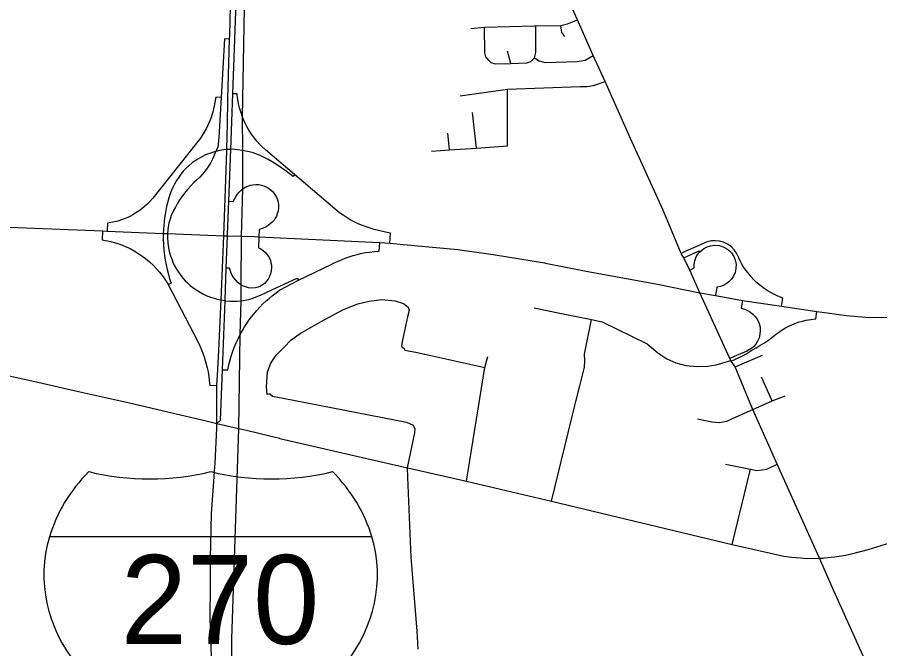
# Model space of a CAD drawing. Extents: x 1755200 to 1902939, y 644115 to 788070.
# Drawn here: x 1792682 to 1802380, y 715838 to 722940 of the extents above; entities that cross this region are included whole.
import ezdxf

# ---------------------------------------------------------------- set-up
doc = ezdxf.new("R2010")
doc.units = 0
for name, color, linetype in [('GM_X_City_Street', 7, 'Continuous'), ('GM_X_County_Road', 7, 'Continuous'), ('GM_X_Interchange_Ramps', 7, 'Continuous'), ('GM_X_Interstate_Route', 7, 'Continuous'), ('GM_X_Interstate_Shield', 7, 'Continuous'), ('GM_X_Township', 7, 'Continuous')]:
    doc.layers.add(name, color=color, linetype=linetype)

msp = doc.modelspace()

# ---------------------------------------------------------------- linework, layer by layer
at = {"layer": 'GM_X_City_Street'}
for points in [[(1799922.1, 720819), (1799578.3, 721577.4), (1799292.9, 722218.4), (1799156.2, 722510.8), (1798981.2, 722912.2), (1798799.7, 723311.4), (1798618.3, 723721.3), (1798281.2, 724477)], [(1797783.5, 722813.8), (1797937.3, 722828.9), (1798497.6, 722843.5)], [(1797984.3, 722455.3), (1797950.1, 722495.9), (1797938.4, 722540.5), (1797937.3, 722828.9)], [(1798497.6, 722843.5), (1798511.6, 722843.9), (1798793.4, 722848.1), (1798870.2, 722865.2), (1798981.2, 722912.2)], [(1798498.7, 722485.2), (1798513.7, 722545), (1798511.6, 722843.9)], [(1798838.2, 722724.3), (1798806.1, 722769.2), (1798793.4, 722848.1)], [(1798231.9, 722419.1), (1798192.9, 722556.6)], [(1797984.3, 722455.3), (1798007.7, 722429.7), (1798056.8, 722414.8), (1798231.9, 722419.1), (1798413.3, 722425.5), (1798456, 722440.4), (1798498.7, 722485.2)], [(1798498.7, 722485.2), (1798550, 722448.9), (1798616.2, 722431.9), (1798740, 722434), (1798979.1, 722440.4), (1799068.7, 722457.5), (1799156.2, 722510.8)], [(1797662.7, 722056.2), (1798193.5, 722130.8), (1799013.2, 722160.7), (1799087.9, 722160.7), (1799160.5, 722173.6), (1799292.9, 722218.4)], [(1798195.6, 721494.8), (1798193.5, 722130.8)], [(1797845.9, 721469.3), (1797801.9, 721867)], [(1797543.6, 721447.2), (1797523.9, 721636.6)], [(1797340.2, 721432.3), (1797543.6, 721447.2), (1797845.9, 721469.3), (1798195.6, 721494.8)], [(1800045.9, 720527.8), (1799941.2, 720777), (1799922.1, 720819)], [(1800948.6, 718535.3), (1800753.9, 719007.9), (1800708.9, 719072), (1800705, 719079.7), (1800693, 719103.5), (1800357.9, 719840.5), (1800244.5, 720096.6), (1800177.4, 720232.6), (1800148.1, 720284.6), (1800045.9, 720527.8)], [(1795521.6, 718706.5), (1795493, 718698.3), (1795483.1, 718784.8), (1795495.2, 718953), (1795533.7, 719050.4), (1795592, 719141.2), (1795684.5, 719231.2), (1795762.6, 719311.5), (1795862.7, 719383.3), (1796090.5, 719514.1), (1796350.5, 719652.1), (1796510.5, 719716.3), (1796637.6, 719747.3), (1796776.5, 719766), (1796930.5, 719750.1), (1797024, 719719.8), (1797077.2, 719680.3), (1797088.3, 719641.9), (1797070.5, 719572.2), (1797012, 719308.8), (1797007, 719268.8), (1797004.2, 719236.8), (1797033.7, 719214)], [(1798492.7, 719672.1), (1798764.4, 719615), (1799138.2, 719540), (1799257.6, 719514), (1799763.2, 719266.6), (1799884.2, 719166), (1799984.7, 719096.8), (1800088.6, 719053.5), (1800198.2, 719024.9), (1800325.1, 719013), (1800443.9, 719017.4), (1800540.3, 719032.5), (1800705, 719079.7)], [(1798963.2, 718617.1), (1799007, 718794.4), (1799059.2, 719004.4), (1799063.4, 719079.1), (1799060.9, 719152.2), (1799138.2, 719540)], [(1790084.9, 719483.7), (1790089.4, 719482.8), (1790568.8, 719379), (1790869, 719309), (1791383, 719177.3), (1791626.9, 719116.3), (1792323, 718971.1), (1792577.4, 718912.4), (1792962.2, 718825.1)], [(1797033.7, 719214), (1797037.3, 719195.8), (1797163.1, 719174.7), (1797262.7, 719152.4)], [(1797262.7, 719152.4), (1797264.5, 719152), (1797941, 719001.1)], [(1800753.9, 719007.9), (1801059.6, 719139.3)], [(1797731.7, 717722.3), (1797941, 719001.1), (1797972.1, 719124.6)], [(1801168.2, 718626.3), (1801050.6, 718892.1)], [(1792962.2, 718825.1), (1793370, 718732.6), (1793943.5, 718601.8), (1794758.7, 718410.9), (1794760.1, 718410.6)], [(1795521.6, 718706.5), (1795553.7, 718680.3), (1795673, 718657), (1797059.1, 718386.2), (1797131.9, 718351.3)], [(1800951, 718529.6), (1801168.2, 718626.3), (1801316, 718680.4)], [(1798688.8, 717498.6), (1798952, 718572), (1798963.2, 718617.1)], [(1800329.8, 718424), (1800490.2, 718391.4), (1800575.4, 718381.5), (1800659.4, 718398.6), (1800763.6, 718444.2), (1800951, 718529.6)], [(1801783.4, 712231.7), (1801887.9, 712659.7), (1801997.9, 713163.1), (1802166.2, 713923.2), (1802256.5, 714341), (1802306.7, 714573.8), (1802366, 714854.1), (1802375.2, 714962.6), (1802376.2, 715028.5), (1802376.2, 715109.6), (1802372.8, 715188.8), (1802350.8, 715313.4), (1802311.5, 715466.5), (1802266.9, 715592.7), (1802098.4, 715964.8), (1801848.6, 716523.8), (1801702.5, 716856.8), (1801227.1, 717912.4), (1800951, 718529.6), (1800948.6, 718535.3)], [(1795170.9, 718315.3), (1795173.2, 718314.8), (1795273.4, 718290.7)], [(1795273.4, 718290.7), (1795632.2, 718204.6)], [(1797070.7, 717873.7), (1797152.2, 718266.8), (1797158.1, 718310.5), (1797131.9, 718351.3)], [(1795632.2, 718204.6), (1795633.7, 718204.2), (1797070.7, 717873.7)], [(1800643.6, 717914.1), (1800927.2, 717856.8), (1800996.4, 717843.2), (1801108.2, 717859.2), (1801227.1, 717912.4)], [(1797070.7, 717873.7), (1797122.1, 717861.9)], [(1797075.1, 717769), (1797070.7, 717873.7)], [(1797122.1, 717861.9), (1797731.7, 717722.3), (1798688.8, 717498.6), (1800720.5, 717010.2), (1801299.7, 716878.2), (1801392.7, 716866.2), (1801488.8, 716860.2), (1801560.8, 716854.2), (1801702.5, 716856.8)], [(1800720.5, 717010.2), (1800927.2, 717856.8)], [(1801702.5, 716856.8), (1801742.3, 716857.2), (1801756.4, 716858.8)]]:
    msp.add_lwpolyline(points, dxfattribs=at)
at = {"layer": 'GM_X_County_Road'}
for points in [[(1794760.1, 718410.6), (1794927.6, 718370.2), (1795170.9, 718315.3)], [(1797189, 715833.2), (1797177, 716035.5), (1797112.4, 716867.6), (1797075.1, 717769)], [(1801756.4, 716858.8), (1801874.4, 716872.2), (1801992.9, 716891.7), (1802093.5, 716911.2), (1802251, 716954.7), (1802491.1, 717027.5)]]:
    msp.add_lwpolyline(points, dxfattribs=at)
at = {"layer": 'GM_X_Interchange_Ramps'}
for points in [[(1794927.6, 718370.2), (1794966.4, 718408), (1794988.4, 718973.1), (1795018.8, 719753), (1795033.1, 720119.2), (1795047.2, 720481), (1795047.8, 720496.4), (1795061.4, 720870.5), (1795082.5, 721454.1), (1795105.1, 722080.1), (1795142.2, 723105.2), (1795083.1, 723108)], [(1795069.1, 722693.1), (1795011.5, 722695.9), (1794975.3, 722036.8), (1794950.6, 721588.5), (1794939.4, 721478), (1794916.6, 721431.1), (1794905.7, 721408.8), (1794880.8, 721353.1), (1794858, 721308), (1794838.9, 721275.2), (1794809.6, 721231.2), (1794784.2, 721197.8), (1794762.1, 721171.6), (1794734.1, 721141.6), (1794698, 721109.2), (1794667.7, 721080.2), (1794634, 721045.2), (1794597.6, 721004.2), (1794563.3, 720961.8), (1794533, 720920.7), (1794508.5, 720884.7), (1794482.2, 720842.7), (1794460.2, 720804.3), (1794436.5, 720759), (1794413.3, 720709.2), (1794399.9, 720670.7), (1794388.4, 720624.7), (1794380.5, 720581.4), (1794376.3, 720547.5), (1794373.4, 720507.5), (1794373, 720501.5), (1794372.6, 720463.1), (1794376.3, 720400.1), (1794383.6, 720347.8), (1794392.1, 720306.6), (1794406.2, 720255.7), (1794419, 720218.9), (1794432.1, 720186.6), (1794451.4, 720145.7), (1794472.7, 720107), (1794493.8, 720073.4), (1794520.5, 720036.1), (1794546.9, 720003.4), (1794570.9, 719976.9), (1794596.3, 719951.5), (1794627, 719923.9), (1794666.8, 719892.4), (1794700.2, 719869.3), (1794737.8, 719846.4), (1794776.2, 719826.2), (1794815.7, 719808.2), (1794865.4, 719789.6), (1794899.2, 719779.2), (1794930.5, 719771), (1794970.9, 719761.3), (1794974.9, 719760.6), (1795018.8, 719753), (1795022.4, 719752.4), (1795070.7, 719747.6), (1795108.6, 719746.3), (1795154.1, 719747.3), (1795201.2, 719751.5), (1795245.6, 719758.5), (1795283.1, 719766.7), (1795323.1, 719777.9), (1795370.3, 719794.4), (1795415.7, 719814.1), (1795543.6, 719874.2), (1795830.2, 720006.7), (1795843.3, 719981.8)], [(1796871.7, 720400.4), (1796880.1, 720511.7), (1796821, 720521.8), (1796743.4, 720541.8), (1796695.5, 720553.7), (1796648.7, 720567.5), (1796603.7, 720582.7), (1796562.6, 720598.4), (1796516.8, 720617.9), (1796476.5, 720637), (1796427, 720663.1), (1796381.5, 720689.7), (1796333.8, 720720.5), (1796304.2, 720741.4), (1796278.1, 720760.9), (1795800.7, 721169.7), (1795474, 721449.3), (1795435.8, 721483.7), (1795407.1, 721512.4), (1795375.4, 721547.3), (1795348.6, 721579.9), (1795315.3, 721625.3), (1795287, 721669.1), (1795262.4, 721712.6), (1795237, 721764.4), (1795215.1, 721817.3), (1795198.6, 721865.2), (1795182.5, 721921.3), (1795170.7, 721967.6), (1795161.4, 722015.7), (1795155.4, 722059.4), (1795153.9, 722077.8), (1795105.1, 722080.1)], [(1794975.3, 722036.8), (1794913.9, 722039.7), (1794897.2, 721943.7), (1794889.9, 721909.5), (1794880.9, 721873.9), (1794870.9, 721840.2), (1794861, 721810.9), (1794847.2, 721774.3), (1794826.2, 721726.2), (1794805.6, 721685.1), (1794785.4, 721649.2), (1794765.5, 721617), (1794741.3, 721581.6), (1794696.4, 721523.9), (1794205, 720906.8), (1794171.6, 720868.2), (1794139.9, 720835.8), (1794114.3, 720812.3), (1794083.2, 720786.4), (1794052.4, 720763.2), (1794017.1, 720739.5), (1793983.8, 720719.6), (1793955.4, 720704.3), (1793924.5, 720689.4), (1793885.6, 720672.9), (1793854.5, 720661.6), (1793812, 720648.4), (1793777.1, 720639.4), (1793697.4, 720623.1), (1793692.1, 720534.8)], [(1795800.7, 721169.7), (1795783.4, 721149.4), (1795725.2, 721194.7), (1795692.4, 721218.6), (1795659, 721241.4), (1795619.1, 721269.5), (1795578.4, 721295.8), (1795547, 721314.5), (1795503.4, 721338.6), (1795415.2, 721383.2), (1795364.4, 721405.1), (1795322.3, 721419.9), (1795217.6, 721439.7), (1795098.1, 721454.6), (1795082.5, 721454.1), (1795051.9, 721453.1), (1795039.3, 721451.9), (1795006.2, 721448.7), (1794955.8, 721440.5), (1794916.6, 721431.1), (1794898.3, 721426.7), (1794854.7, 721412.8), (1794800.8, 721391.4), (1794765.2, 721374.4), (1794725.4, 721352.6), (1794688.5, 721329.3), (1794654.5, 721305), (1794610.7, 721268.9), (1794578.4, 721238.4), (1794549.1, 721207.3), (1794521.3, 721174), (1794497.8, 721142.4), (1794471.6, 721102.6), (1794448.7, 721062.3), (1794426.9, 721017.2), (1794409.8, 720975.1), (1794388.5, 720909.3), (1794372.7, 720852.8), (1794362.3, 720810.1), (1794353.3, 720768.1), (1794345.7, 720727), (1794339.1, 720684.9), (1794333.4, 720641.1), (1794329.1, 720597.9), (1794325.9, 720552.4), (1794324.3, 720509.5), (1794323.8, 720496.4), (1794323.6, 720443.2), (1794325.8, 720382.3), (1794330.5, 720318.8), (1794337.3, 720260), (1794345.4, 720207.1), (1794355.2, 720155.2), (1794366.9, 720102.7), (1794381.9, 720046), (1794395.8, 719999.6), (1794412.2, 719950.8), (1794377.9, 719932.7)], [(1795061.4, 720870.5), (1795108.6, 720868.3), (1795144.8, 720928.7), (1795159.9, 720950.4), (1795176.8, 720971.4), (1795197.3, 720992.8), (1795220.4, 721011.8), (1795245, 721027.6), (1795274.5, 721041.8), (1795300.1, 721050.5), (1795330.5, 721057), (1795364.5, 721059.8), (1795397.5, 721058.1), (1795428.7, 721052.5), (1795466.6, 721039.7), (1795495.6, 721025.1), (1795519.9, 721008.8), (1795547.1, 720984.9), (1795571.4, 720956.2), (1795582.6, 720939.3), (1795595.4, 720915.6), (1795606.8, 720886.7), (1795614.1, 720859.4), (1795618.4, 720829), (1795619, 720798), (1795615, 720762.8), (1795606.5, 720729.9), (1795596.2, 720703.7), (1795583.2, 720679.1), (1795569.2, 720658.4), (1795548.3, 720634.9), (1795526.3, 720615.2), (1795505.2, 720599.4), (1795480.4, 720584.2), (1795448.7, 720569), (1795402.6, 720552.5), (1795399.8, 720471.8)], [(1793642, 720536.8), (1793636.1, 720438), (1793734.5, 720417.1), (1793781.8, 720404.4), (1793825.2, 720390.6), (1793866.6, 720375.4), (1793907.4, 720358.4), (1793950.4, 720338.1), (1793995.4, 720314.1), (1794038.2, 720288.5), (1794083.7, 720258), (1794125.5, 720226.7), (1794171.1, 720188.4), (1794215.3, 720146.6), (1794252.1, 720107.7), (1794281.4, 720073.5), (1794311.8, 720034.4), (1794340.3, 719993.8), (1794377.9, 719932.7), (1794718.2, 719287.6), (1794736.8, 719246.1), (1794755.5, 719200.2), (1794770, 719161.2), (1794784.2, 719119.2), (1794796.1, 719080), (1794807.3, 719039), (1794817.4, 718997.4), (1794827.1, 718950.4), (1794835.8, 718899.6), (1794841.3, 718859.6), (1794845.1, 718826.2), (1794847.3, 718800.2), (1794927.9, 718800.7)], [(1794988.4, 718973.1), (1795049.8, 718973.5), (1795066.4, 719046.9), (1795076.6, 719086.4), (1795088.4, 719127), (1795104.1, 719175), (1795123.1, 719226.6), (1795144.7, 719278.9), (1795168.5, 719330.3), (1795189.8, 719372.2), (1795214.4, 719416.8), (1795238.7, 719457.3), (1795264.3, 719496.9), (1795291.6, 719536.1), (1795316.6, 719569.8), (1795341.9, 719601.7), (1795376, 719642.1), (1795410.6, 719680.1), (1795445.1, 719715.3), (1795478.6, 719747.1), (1795512.9, 719777.8), (1795548.2, 719807.3), (1795578.1, 719830.7), (1795610.6, 719854.9), (1795632.8, 719870.5), (1795843.3, 719981.8), (1796210.9, 720158.2), (1796239.3, 720173.1), (1796289.4, 720197.1), (1796333.9, 720216.3), (1796369, 720230.1), (1796414.6, 720246.2), (1796460.8, 720260.6), (1796503.7, 720272.3), (1796542.6, 720281.5), (1796596.9, 720292.3), (1796643.2, 720299.5), (1796698.2, 720306), (1796750.4, 720310.1), (1796757.6, 720405.8)], [(1795399.8, 720471.8), (1795395.3, 720345.2), (1795420.1, 720333.6), (1795446.9, 720315.9), (1795472.6, 720293.5), (1795496.2, 720265.6), (1795514.3, 720236.3), (1795527.9, 720205.1), (1795535.3, 720179.6), (1795540.3, 720150), (1795541.5, 720120.8), (1795538.7, 720089.1), (1795530.5, 720054), (1795519, 720024.4), (1795503.2, 719995.9), (1795487, 719973.9), (1795461.2, 719947), (1795438.9, 719929.5), (1795416.3, 719915.6), (1795390.9, 719903.7), (1795362.5, 719896.5), (1795319, 719893.4), (1795280.6, 719897.3), (1795247.1, 719906.3), (1795220.3, 719917.5), (1795201.8, 719928.3), (1795191.8, 719934.1), (1795166.7, 719953.9), (1795140.5, 719981.7), (1795119.2, 720009.2), (1795099.9, 720037), (1795086.5, 720062.6), (1795078.6, 720082.7), (1795069.2, 720118.1), (1795033.1, 720119.2)], [(1801274.6, 719690.3), (1801290.8, 719779.2), (1801225.1, 719807.3), (1801188.3, 719824.9), (1801154.7, 719842.9), (1801126.7, 719859.4), (1801093.1, 719881.2), (1801064.3, 719901.6), (1801028.2, 719930), (1800995.6, 719958.3), (1800961.8, 719990.8), (1800930, 720024.9), (1800894.6, 720067.6), (1800872.9, 720096.8), (1800853.1, 720125.9), (1800829.1, 720164.8), (1800808.7, 720202), (1800793.7, 720232.4), (1800769.9, 720285), (1800743.7, 720323.2), (1800711.8, 720356.3), (1800673.9, 720384.5), (1800623.2, 720409.4), (1800577.6, 720422), (1800534.2, 720426.7), (1800486.6, 720424.2), (1800437.6, 720412.9), (1800192.6, 720306.4), (1800148.1, 720284.6)], [(1800177.4, 720232.6), (1800223.8, 720256.3), (1800348.5, 720313), (1800354.3, 720299.3)], [(1800244.5, 720096.6), (1800293.8, 720121.4), (1800293.9, 720160.8), (1800300.8, 720200.6), (1800317.3, 720245), (1800335.3, 720275.4), (1800354.3, 720299.3), (1800384.7, 720323.9), (1800409.9, 720344.4), (1800437.8, 720358.3), (1800477.2, 720370.8), (1800524.6, 720376.5), (1800576.6, 720371.7), (1800619.2, 720358.6), (1800650.9, 720342.5), (1800682.5, 720319.7), (1800711.5, 720289.9), (1800737.9, 720249.9), (1800755.4, 720206.5), (1800763.6, 720163.6), (1800763.1, 720112.9), (1800753, 720067.4), (1800736.8, 720029.4), (1800712.3, 719992.5), (1800683.3, 719962.5), (1800653.4, 719940.4), (1800620.5, 719923.4), (1800587.3, 719912.2), (1800547.4, 719905.6), (1800531.8, 719809.3)], [(1800835.4, 719754.2), (1800819.9, 719669), (1800859.1, 719655.7), (1800893.5, 719642.4), (1800926.9, 719623.3), (1800953.6, 719602.4), (1800982, 719572.2), (1801006.4, 719535.2), (1801023.1, 719497), (1801033.5, 719455), (1801036.5, 719417.2), (1801033, 719374.7), (1801023.4, 719336.1), (1801006.2, 719296.8), (1800984.8, 719263.7), (1800958.7, 719234.7), (1800928.4, 719212.6), (1800885.5, 719183.2), (1800742, 719123.9), (1800693, 719103.5)], [(1800708.9, 719072), (1800744.5, 719088), (1800875.4, 719151.8), (1800942, 719195.5), (1800991.8, 719222.8), (1801032.6, 719246.8), (1801083.5, 719279.1), (1801128, 719309.7), (1801164.1, 719336.1), (1801204.3, 719370), (1801244.1, 719399.7), (1801281.7, 719424.7), (1801320.4, 719447.4), (1801363.4, 719469.5), (1801417.2, 719492.8), (1801464.1, 719509.6), (1801509.7, 719522.9), (1801553.3, 719533), (1801603.1, 719541.6), (1801662.3, 719548.7), (1801672.4, 719630.8)]]:
    msp.add_lwpolyline(points, dxfattribs=at)
at = {"layer": 'GM_X_Interstate_Route'}
for points in [[(1795070.7, 722739.2), (1795081.6, 723061.9)], [(1795050.8, 722008.7), (1795051.2, 722027.6), (1795069.1, 722693.1), (1795070.7, 722739.2)], [(1795045.4, 721745.5), (1795050.8, 722008.7)], [(1795027.8, 721113.7), (1795039, 721437.7), (1795039.3, 721451.9), (1795045.4, 721745.5)], [(1795005.9, 720482.1), (1795027.8, 721113.7)], [(1791348.1, 720628.8), (1791352.6, 720628.6), (1793642, 720536.8), (1793692.1, 720534.8), (1794324.3, 720509.5), (1794373.4, 720507.5), (1795005.9, 720482.1)], [(1794947.1, 719193), (1794974.9, 719760.6), (1795005.9, 720482.1)], [(1795005.9, 720482.1), (1795047.2, 720481), (1795203.8, 720476.9), (1795350.5, 720473.1)], [(1795350.5, 720473.1), (1795399.8, 720471.8), (1796757.6, 720405.8), (1796871.7, 720400.4), (1797026.9, 720385.6)], [(1797026.9, 720385.6), (1797635.3, 720327.5), (1798031.9, 720272.3), (1798609.1, 720176.9), (1798623, 720174.1)], [(1798623, 720174.1), (1799077.9, 720084.5), (1799882, 719938), (1800357.9, 719840.5)], [(1800357.9, 719840.5), (1800531.8, 719809.3), (1800835.4, 719754.2), (1801274.6, 719690.3), (1801672.4, 719630.8), (1801786.7, 719615)], [(1801786.7, 719615), (1802007.2, 719584.4), (1802264.3, 719564.6), (1802967.9, 719565.6), (1803502.3, 719541.5), (1803710.7, 719521.1), (1804190.8, 719478.9), (1804943.9, 719360.9), (1805475.1, 719257.3)], [(1794933.4, 718912.7), (1794947.1, 719193)], [(1794927.8, 718671.5), (1794927.9, 718800.7), (1794933.4, 718912.7)], [(1794927.7, 718456.3), (1794927.8, 718671.5)], [(1794925, 718316.7), (1794927.6, 718370.2), (1794927.7, 718456.3)], [(1794900.7, 717835), (1794905.8, 717926.1), (1794925, 718316.7)], [(1794854.8, 716550.3), (1794855, 716580.4), (1794856.5, 716854.1), (1794864.8, 717359.4), (1794897, 717770.3), (1794900.7, 717835)], [(1794884.6, 715264.7), (1794882.7, 715319.9), (1794852.8, 716180.4), (1794854.8, 716550.3)]]:
    msp.add_lwpolyline(points, dxfattribs=at)
at = {"layer": 'GM_X_Interstate_Shield'}
msp.add_line((1796670.1, 717095), (1793044.1, 717095), dxfattribs=at)
msp.add_line((1796670.1, 717095), (1793044.1, 717095), dxfattribs=at)
for centre, start_param, end_param in [((1795325.9, 716666.5), 2.47259, 2.911027), ((1794172.2, 719622.6), 4.415841, 5.008937), ((1795542, 719622.6), 4.415841, 5.008937), ((1794388.4, 716666.5), 0.230566, 0.669003), ((1795325.9, 716666.5), 2.911027, 4.511031), ((1794388.4, 716666.5), 4.913747, 6.513751)]:
    msp.add_ellipse(centre, major_axis=(2343.8, 0), ratio=0.8, start_param=start_param, end_param=end_param, dxfattribs=at)
at = {"layer": 'GM_X_Township'}
msp.add_lwpolyline([(1795067.8, 712958), (1795095.5, 715946.8), (1795173.2, 718314.8), (1795189.8, 719372.2), (1795201.2, 719751.5), (1795201.8, 719928.3), (1795203.8, 720476.9), (1795220.4, 721011.8), (1795217.6, 721439.7), (1795215.1, 721817.3), (1795248.2, 723669.1), (1795805.7, 723775.7), (1796352.1, 723865.5), (1796655.8, 723912.9), (1796866.6, 723946.3), (1797096.3, 723990.1), (1797207.1, 724021), (1797336.4, 724065.8), (1797633.7, 724194.4), (1798281.3, 724477), (1799900.2, 725182.9), (1800858.1, 725605.3), (1802383, 726270.1)], dxfattribs=at)

# ---------------------------------------------------------------- texts
at = {"layer": 'GM_X_Interstate_Shield'}
msp.add_text('270', height=1000, dxfattribs=at).set_placement((1793847.2, 715891.9))

doc.saveas('drawing.dxf')
